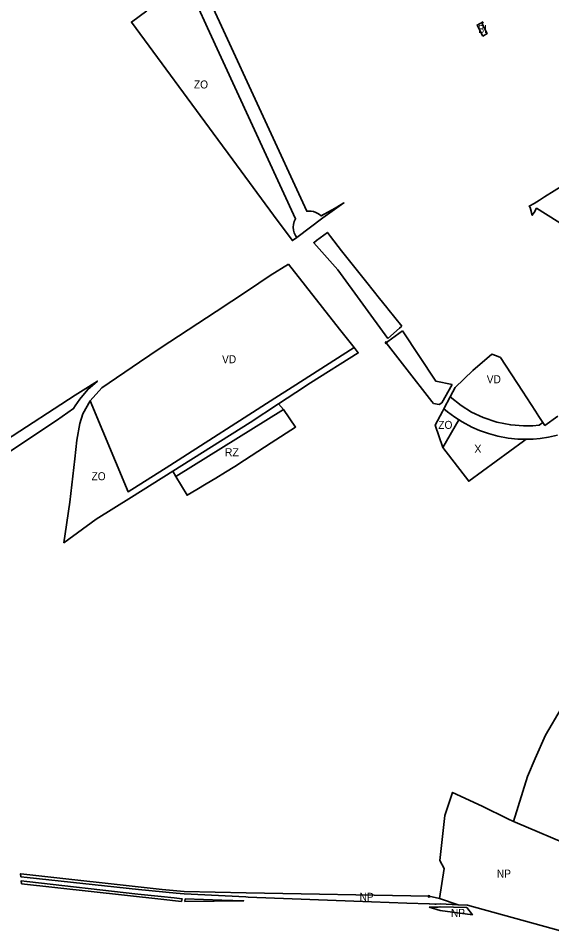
# Model space of a CAD drawing. Extents: x -650276 to -642489, y -1074311 to -1066658.
# Drawn here: x -648027 to -647227, y -1073041 to -1071673 of the extents above; entities that cross this region are included whole.
import ezdxf

# ---------------------------------------------------------------- set-up
doc = ezdxf.new("R2010")
doc.units = 0
doc.header["$LTSCALE"] = 4.8
doc.header["$PDMODE"] = 32
doc.header["$PDSIZE"] = 2.4
for name, color, linetype, lineweight in [('15', 7, 'Continuous', 35), ('2', 7, 'Continuous', 35), ('24', 7, 'Continuous', 35), ('35', 7, 'Continuous', 35), ('42', 7, 'Continuous', 35), ('46', 7, 'Continuous', 35), ('48', 7, 'Continuous', 35), ('51', 7, 'Continuous', 35), ('8', 7, 'Continuous', 35)]:
    doc.layers.add(name, color=color, linetype=linetype, lineweight=lineweight)
doc.layers.add('62', color=7, linetype='Continuous')

msp = doc.modelspace()

# ---------------------------------------------------------------- linework, layer by layer
at = {"layer": '15'}
msp.add_lwpolyline([(-647795.4, -1072352.415), (-647679.66, -1072279.15), (-647637.082, -1072251.377), (-647629.67, -1072259.82), (-647791.198, -1072360.119)], close=True, dxfattribs=at)
for points in [[(-647629.67, -1072259.82), (-647637.082, -1072251.377), (-647679.66, -1072279.15)], [(-647679.66, -1072279.15), (-647795.4, -1072352.415), (-647791.198, -1072360.119), (-647629.67, -1072259.82)]]:
    msp.add_lwpolyline(points, dxfattribs=at)
at = {"layer": '2'}
for points in [[(-647330.34, -1071678.82), (-647339.211, -1071683.431), (-647330.73, -1071700.09)], [(-647330.73, -1071700.09), (-647324.21, -1071696.2), (-647331.65, -1071681.7), (-647330.34, -1071678.82)]]:
    msp.add_lwpolyline(points, dxfattribs=at)
at = {"layer": '24'}
for points in [[(-647725.629, -1071678.373), (-647735.352, -1071657.117), (-647741.34, -1071644.028), (-647753.065, -1071625.201), (-647767.784, -1071606.225), (-647782.408, -1071590.847), (-647798.911, -1071576.526), (-647817.375, -1071563.458), (-647834.953, -1071553.406)], [(-647782.97, -1071619.278), (-647769.498, -1071636.647), (-647758.994, -1071653.513), (-647743.48, -1071687.426), (-647611.514, -1071974.086)], [(-647570.747, -1071972.644), (-647538.922, -1071950.099), (-647551.962, -1071958.049), (-647573.283, -1071969.627), (-647575.415, -1071967.709), (-647577.881, -1071965.979), (-647581.036, -1071964.346), (-647584.363, -1071963.196), (-647588.064, -1071962.51), (-647591.518, -1071962.387), (-647594.731, -1071962.714), (-647725.614, -1071678.405), (-647726.774, -1071675.885), (-647725.629, -1071678.373)], [(-647611.514, -1071974.086), (-647613.455, -1071978.031), (-647614.654, -1071982.238), (-647615.083, -1071986.65), (-647614.76, -1071990.762), (-647613.637, -1071995.081), (-647611.779, -1071999.069), (-647609.808, -1072001.962), (-647570.747, -1071972.644)], [(-647542.57, -1072021.99), (-647558.97, -1072000.62), (-647563.77, -1071994.38), (-647579.885, -1072006.501)], [(-647579.885, -1072006.501), (-647584.202, -1072009.747), (-647547.916, -1072050.439), (-647473.022, -1072153.375)], [(-647452.23, -1072134.91), (-647472.86, -1072109.13), (-647474.72, -1072106.81), (-647485.6, -1072093.2), (-647504.73, -1072069.29), (-647542.57, -1072021.99)], [(-647451.21, -1072142.08), (-647473.12, -1072157.91), (-647475.57, -1072159.74), (-647475.57, -1072159.74)], [(-647473.022, -1072153.375), (-647455.83, -1072137.96), (-647452.23, -1072134.91)], [(-647376.68, -1072222.29), (-647401.221, -1072217.342), (-647451.21, -1072142.08)], [(-647475.57, -1072159.74), (-647447.73, -1072195.72), (-647407.34, -1072247.93)], [(-648050.276, -1072330.025), (-647969.894, -1072276.479), (-647944.45, -1072258.458), (-647941.77, -1072254.45), (-647934.9, -1072244.55), (-647923.16, -1072229.85), (-647908.5, -1072217.29), (-647933.95, -1072233.18), (-647942.21, -1072238.54), (-648046.69, -1072306.3)], [(-647407.34, -1072247.93), (-647404.45, -1072250.66), (-647396.25, -1072252.14), (-647392.34, -1072250.02), (-647376.68, -1072222.29)], [(-647218.35, -1072269.67), (-647237.6, -1072283.78), (-647240.55, -1072279.42), (-647246.206, -1072283.328), (-647255.671, -1072284.192), (-647269.579, -1072284.489), (-647288.769, -1072283.003), (-647309.416, -1072278.875), (-647330.032, -1072271.935), (-647347.382, -1072263.623), (-647363.317, -1072253.632), (-647379.422, -1072240.675), (-647389.072, -1072258.845), (-647383.813, -1072263.219), (-647372.858, -1072271.363), (-647361.521, -1072278.584), (-647347.369, -1072286.111), (-647335.382, -1072291.341), (-647321.953, -1072296.073), (-647308.157, -1072299.786), (-647292.715, -1072302.646), (-647278.108, -1072304.147), (-647271.395, -1072304.452), (-647265.793, -1072304.439), (-647265.793, -1072304.439), (-647255.16, -1072304.123), (-647244.428, -1072303.192), (-647232.368, -1072301.4), (-647218.5, -1072298.335)]]:
    msp.add_lwpolyline(points, dxfattribs=at)
msp.add_point((-647475.57, -1072159.74), dxfattribs=at)
at = {"layer": '35'}
for points in [[(-647194.903, -1071913.941), (-647238.1, -1071941), (-647245.71, -1071945.77), (-647253.67, -1071950.76), (-647261.12, -1071954.82), (-647259.7, -1071957.06), (-647256.53, -1071968.64), (-647253.85, -1071964.38), (-647249.92, -1071958.12), (-647201.53, -1071988.71)], [(-647621.97, -1072041.73), (-647649.76, -1072059.06), (-647683.63, -1072081.94), (-647730.53, -1072112.84), (-647814.58, -1072167.67), (-647845.58, -1072188.94), (-647901.91, -1072227.6), (-647919.68, -1072247.09), (-647862.615, -1072383.084)], [(-647523.71, -1072167.071), (-647545.44, -1072139.35), (-647621.97, -1072041.73)], [(-647862.615, -1072383.084), (-647800.2, -1072343.615), (-647642.504, -1072242.974), (-647616.719, -1072226.154), (-647523.71, -1072167.071)]]:
    msp.add_lwpolyline(points, dxfattribs=at)
msp.add_lwpolyline([(-647246.563, -1072270.214), (-647251.85, -1072262.12), (-647271.38, -1072232.23), (-647304.32, -1072181.81), (-647310.33, -1072179.58), (-647317.33, -1072176.99), (-647345.42, -1072201.58), (-647372.1, -1072226.89), (-647375.551, -1072233.387), (-647379.422, -1072240.675), (-647363.317, -1072253.632), (-647347.382, -1072263.623), (-647330.032, -1072271.935), (-647309.416, -1072278.875), (-647288.769, -1072283.003), (-647269.579, -1072284.489), (-647255.671, -1072284.192), (-647246.206, -1072283.328), (-647240.55, -1072279.42)], close=True, dxfattribs=at)
at = {"layer": '42'}
for points in [[(-647758.889, -1071653.742), (-647743.48, -1071687.426), (-647611.514, -1071974.086), (-647613.455, -1071978.031), (-647614.654, -1071982.238), (-647615.083, -1071986.65), (-647614.76, -1071990.762), (-647613.637, -1071995.081), (-647611.779, -1071999.069), (-647609.808, -1072001.962), (-647616.12, -1072006.7), (-647621.06, -1072000), (-647644.38, -1071968.3), (-647705.291, -1071885.501), (-647727.85, -1071854.86), (-647857.52, -1071678.92), (-647834.345, -1071661.969)], [(-647637.082, -1072251.377), (-647611.306, -1072234.563), (-647589.02, -1072219.66), (-647517.51, -1072174.98), (-647523.71, -1072167.071), (-647616.719, -1072226.154), (-647642.504, -1072242.974), (-647800.2, -1072343.615)], [(-647800.2, -1072343.615), (-647862.615, -1072383.084), (-647919.68, -1072247.09), (-647930.36, -1072266.38), (-647934.86, -1072280.99), (-647939.26, -1072306.1), (-647942.54, -1072333.82), (-647950.2, -1072398.61), (-647956.786, -1072446.511), (-647958.82, -1072459.74), (-647910.27, -1072424.51), (-647857.52, -1072391.14), (-647795.4, -1072352.415)], [(-647795.4, -1072352.415), (-647679.66, -1072279.15), (-647637.082, -1072251.377)]]:
    msp.add_lwpolyline(points, dxfattribs=at)
msp.add_lwpolyline([(-647390.58, -1072316.75), (-647366.505, -1072275.41), (-647372.858, -1072271.363), (-647383.813, -1072263.219), (-647389.072, -1072258.845), (-647391.3, -1072263.04), (-647401.88, -1072283.4)], close=True, dxfattribs=at)
at = {"layer": '46'}
msp.add_lwpolyline([(-647284.75, -1072877.79), (-647282.31, -1072878.82), (-647192.718, -1072916.582), (-647187.445, -1072918.804), (-647172.48, -1072872.92), (-647155.72, -1072836.46), (-647136.69, -1072808.98), (-647079.74, -1072731.1), (-647025.04, -1072679.96), (-646953.2, -1072627.45), (-646957.5, -1072612.09), (-646973.68, -1072555.68), (-646989.01, -1072513.62), (-646991.24, -1072509.24), (-647063.38, -1072562.42), (-647088.397, -1072580.865), (-647088.4, -1072580.868), (-647146.21, -1072634.02), (-647172.36, -1072661.69), (-647198.77, -1072691.71), (-647212.92, -1072708.05), (-647236.54, -1072748.09), (-647252.29, -1072783.24), (-647263.58, -1072809.97)], close=True, dxfattribs=at)
at = {"layer": '48'}
for points in [[(-647293.317, -1072873.549), (-647293.351, -1072873.533), (-647331.82, -1072854.49), (-647375.92, -1072833.99), (-647387.64, -1072868.69), (-647392.96, -1072918.277), (-647394.87, -1072936.08), (-647388.62, -1072948.03), (-647395.47, -1072993.25), (-647367.45, -1073002.47), (-647353.78, -1073003.1), (-647213.99, -1073041.449), (-647210.396, -1073023.593), (-647207.176, -1073007.598), (-647192.93, -1072936.82), (-647187.445, -1072918.804), (-647192.718, -1072916.582), (-647282.31, -1072878.82), (-647284.75, -1072877.79)], [(-648022.279, -1072971.102), (-647813.331, -1072994.317), (-647782.72, -1072997.397), (-647781.65, -1072993.53), (-647793.59, -1072992.29), (-647813.2, -1072990.26), (-647848.15, -1072986.63), (-648014.58, -1072967.51), (-648022.74, -1072966.57)], [(-647777.337, -1072997.711), (-647689.11, -1072996.49), (-647721.83, -1072995.45), (-647776.77, -1072993.69)], [(-647411.34, -1073005.89), (-647394.782, -1073011.002), (-647346.22, -1073017.52), (-647354.76, -1073006.65), (-647394.59, -1073005.58), (-647395.08, -1073005.64), (-647397.74, -1073005.95), (-647400.27, -1073006.24), (-647400.76, -1073006.29), (-647403.05, -1073006.2)]]:
    msp.add_lwpolyline(points, close=True, dxfattribs=at)
for points in [[(-647685.748, -1072984.544), (-647778.296, -1072982.767), (-647811.752, -1072979.4), (-648023.495, -1072955.875), (-648023.818, -1072955.949), (-648023.37, -1072960.37), (-648014.16, -1072961.36), (-647846.85, -1072979.37), (-647790.52, -1072985.06), (-647778.3, -1072986.29), (-647686.14, -1072990.78)], [(-647686.14, -1072990.78), (-647682.74, -1072990.95), (-647497.35, -1072997.93), (-647444.42, -1072999.87), (-647411.326, -1073001.08)], [(-647411.294, -1072989.813), (-647411.298, -1072989.813), (-647685.748, -1072984.544)], [(-647411.326, -1073001.08), (-647410.791, -1073001.197), (-647410.79, -1073001.1), (-647402.49, -1073001.41), (-647400.55, -1073001.48), (-647394.46, -1073001.23), (-647367.45, -1073002.47), (-647395.47, -1072993.25), (-647411.293, -1072989.813), (-647411.294, -1072989.813)]]:
    msp.add_lwpolyline(points, dxfattribs=at)
msp.add_point((-647411.294, -1072989.813), dxfattribs=at)
at = {"layer": '51'}
msp.add_lwpolyline([(-647390.58, -1072316.75), (-647351.86, -1072367.52), (-647269.52, -1072307.17), (-647265.793, -1072304.439), (-647271.395, -1072304.452), (-647278.108, -1072304.147), (-647292.715, -1072302.646), (-647308.157, -1072299.786), (-647321.953, -1072296.073), (-647335.382, -1072291.341), (-647347.369, -1072286.111), (-647361.521, -1072278.584), (-647366.505, -1072275.41)], close=True, dxfattribs=at)
at = {"layer": '8'}
msp.add_lwpolyline([(-647629.67, -1072259.82), (-647611.51, -1072286.26), (-647648.09, -1072309.95), (-647688.26, -1072336.06), (-647702.35, -1072345.14), (-647716.62, -1072353.95), (-647730.97, -1072362.6), (-647745.32, -1072371.26), (-647759.68, -1072379.91), (-647774.04, -1072388.57), (-647791.198, -1072360.119)], close=True, dxfattribs=at)
for points in [[(-647629.67, -1072259.82), (-647791.198, -1072360.119), (-647774.04, -1072388.57)], [(-647774.04, -1072388.57), (-647759.68, -1072379.91), (-647745.32, -1072371.26), (-647730.97, -1072362.6), (-647716.62, -1072353.95), (-647702.35, -1072345.14), (-647688.26, -1072336.06), (-647648.09, -1072309.95), (-647611.51, -1072286.26), (-647629.67, -1072259.82)]]:
    msp.add_lwpolyline(points, dxfattribs=at)

# ---------------------------------------------------------------- texts
at = {"layer": '62'}
for s, width, p in [('BI', 0.85, (-647337.578, -1071695.247)), ('ZO', 0.95, (-647763.886, -1071778.486)), ('VD', 0.95, (-647721.74, -1072190.495)), ('VD', 0.95, (-647324.74, -1072220.495)), ('ZO', 0.95, (-647397.457, -1072288.915)), ('ZO', 0.95, (-647917.457, -1072365.915)), ('NP', 0.95, (-647309.627, -1072961.756)), ('NP', 0.95, (-647515.505, -1072996.594)), ('NP', 0.95, (-647378.505, -1073020.594))]:
    msp.add_text(s, height=12, dxfattribs=dict(at, width=width)).set_placement(p)
for s, p in [('RZ', (-647717.713, -1072329.92)), ('X', (-647343.371, -1072324.801))]:
    msp.add_text(s, height=12, dxfattribs=at).set_placement(p)

doc.saveas('drawing.dxf')
